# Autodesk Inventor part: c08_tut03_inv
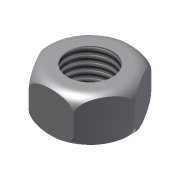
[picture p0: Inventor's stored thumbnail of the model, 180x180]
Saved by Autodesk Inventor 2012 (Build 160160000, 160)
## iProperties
Created: 2010-03
Part Number: c08_tut03_inv
Document SubType Name: Modeling
Designer: CADSoft
Density: 1 g/cm^3
Material: Default
Author: CADSoft
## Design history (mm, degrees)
sketch "Sketch1"
  geometry: C1 r 10 at (0, 0); 1 further point
  constraints: 1 centre point, 1 coincident
  dimensions: "d0" = 20 diameter of C1
extrude "Extrusion1" new body sketch "Sketch1" distance "d1" = 10; taper "d2" = 0 deg
hole "Hole1" diameter "d5" = 10; stored, may be unused: countersink angle "d9" = 90 deg, drill point angle "d11" = 118 deg; dims "d3" = 10, "d4" = 10, "d6" = 6, "d7" = 4, "d8" = 2, "d10" = 8
fillet "Fillet1" dims "d12" = 3, "d13" = 3
sketch "Sketch2"
  geometry: L1 (-10, 0)-(-5, 8.66); L2 (-5, 8.66)-(5, 8.66); L3 (5, 8.66)-(10, 0); L4 (10, 0)-(5, -8.66); L5 (5, -8.66)-(-5, -8.66); L6 (-5, -8.66)-(-10, 0); C1 r 5 at (0, 0); 1 further point
  constraints: 12 end point, 1 centre point, 1 coincident, 13 other
  dimensions: "d19" = 10 diameter of C1
extrude "Extrusion4" sketch "Sketch2" distance "d20" = 10; taper "d21" = 0 deg
thread "Thread1" dims "d22" = 10, "d23" = 0
body "Solid1"
